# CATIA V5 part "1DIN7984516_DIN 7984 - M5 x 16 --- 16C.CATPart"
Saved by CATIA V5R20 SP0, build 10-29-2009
Part number: 1DIN7984516_DIN 7984 - M5 x 16 --- 16C
Revision: ANY
Definition: UNKNOWN
Nomenclature: 1DIN7984516_DIN 7984 - M5 x 16 --- 16C
Source: Unknown
Bounding box of the stored display mesh (mm): x 0 to 19.5, y -4.25 to 4.25, z -4.25 to 4.25
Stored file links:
  C:\Users\Utente\Desktop\IO LAVORO\3D X SITO CF\CUMSA\3D files PW\pw081030\pw081030_ejection\1DIN7984516_DIN 7984 - M5 x 16 --- 16C.CATPart
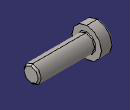
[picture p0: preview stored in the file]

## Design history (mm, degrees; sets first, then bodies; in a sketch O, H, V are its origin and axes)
Body1 "Hex" (main body)
  Solid1: solid without history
